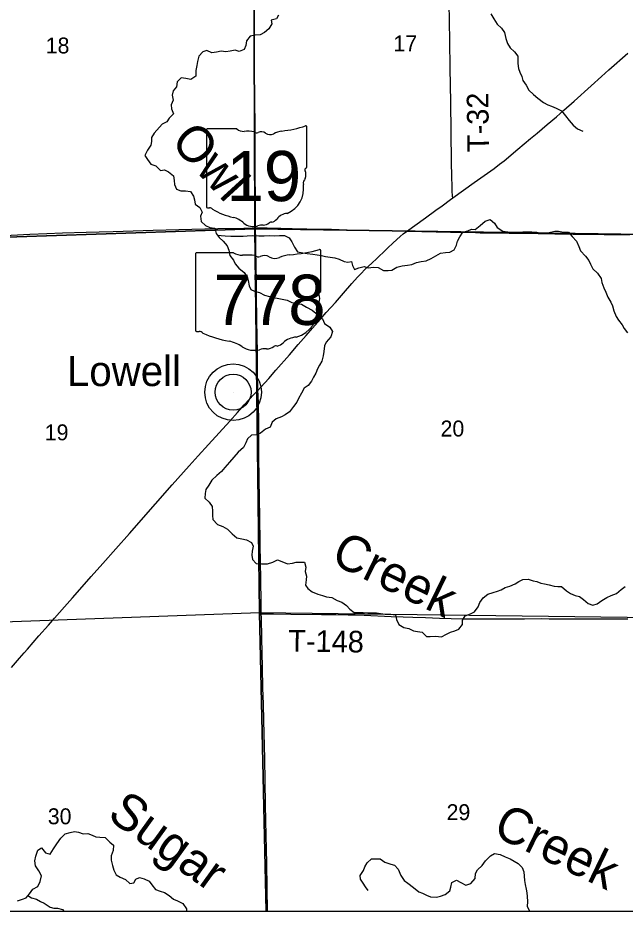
# Model space of a CAD drawing. Extents: x -8.5 to 18.7, y -20.3 to 7.
# Drawn here: x -0.081 to 3.109, y -20.262 to -15.571 of the extents above; entities that cross this region are included whole.
import ezdxf

# ---------------------------------------------------------------- set-up
doc = ezdxf.new("R2010")
doc.units = 0
for name, color, linetype in [('GM_X_Corporation', 7, 'Continuous'), ('GM_X_County_Road', 7, 'Continuous'), ('GM_X_Minor_River', 7, 'Continuous'), ('GM_X_Minor_River_Text', 7, 'Continuous'), ('GM_X_Section', 7, 'Continuous'), ('GM_X_Section_Text', 7, 'Continuous'), ('GM_X_State_Location', 7, 'Continuous'), ('GM_X_State_Route', 7, 'Continuous'), ('GM_X_State_Shield', 7, 'Continuous'), ('GM_X_Township_Road', 7, 'Continuous'), ('GM_X_Township_Road_Text', 7, 'Continuous'), ('GM_X_Unincorporated', 7, 'Continuous'), ('GM_X_Unincorporated_Location', 7, 'Continuous'), ('GM_X_Unincorporated_Text', 7, 'Continuous'), ('SH_Cut_Line', 7, 'Continuous')]:
    doc.layers.add(name, color=color, linetype=linetype)

msp = doc.modelspace()

# ---------------------------------------------------------------- linework, layer by layer
at = {"layer": 'GM_X_Corporation'}
msp.add_lwpolyline([(-0.9232, -20.262), (11.2623, -20.262)], dxfattribs=at)
at = {"layer": 'GM_X_County_Road'}
for points in [[(-0.9189, -16.7512), (-0.8687, -16.7484), (-0.7929, -16.7446), (-0.6837, -16.7394), (-0.6166, -16.736), (-0.5359, -16.7323), (-0.4601, -16.7286), (-0.3458, -16.7228), (-0.287, -16.7201), (-0.2055, -16.7163), (-0.116, -16.7121), (-0.0179, -16.7075), (0.0715, -16.7031), (0.1534, -16.6994), (0.2785, -16.696), (0.3466, -16.6941), (0.4206, -16.6919), (0.6304, -16.6865), (0.7656, -16.6828), (0.9699, -16.6773), (1.1066, -16.6748), (1.1685, -16.6738)], [(1.1981, -18.7004), (1.1972, -18.6597), (1.1957, -18.5019), (1.1947, -18.4473), (1.1926, -18.3219), (1.1904, -18.1964), (1.1886, -18.0939), (1.1869, -17.9965), (1.1854, -17.8676), (1.1849, -17.7758), (1.1845, -17.6854), (1.1832, -17.6048), (1.1826, -17.5813), (1.1822, -17.5672), (1.1812, -17.5528), (1.1797, -17.527)], [(1.231, -20.262), (1.231, -20.2608), (1.2288, -20.1418), (1.2264, -20.0098), (1.2235, -19.8645), (1.2204, -19.7054), (1.2189, -19.5776), (1.216, -19.4624), (1.2113, -19.2613), (1.2092, -19.1755), (1.207, -19.0885), (1.2045, -18.9816), (1.2011, -18.8275), (1.1986, -18.7219), (1.1981, -18.7004)]]:
    msp.add_lwpolyline(points, dxfattribs=at)
at = {"layer": 'GM_X_Minor_River'}
for points in [[(1.2878, -15.5558), (1.2779, -15.5754), (1.2506, -15.5821), (1.2528, -15.6019), (1.2375, -15.6276), (1.2154, -15.6472), (1.1919, -15.6599), (1.1654, -15.662), (1.1396, -15.6672), (1.1198, -15.6921), (1.1174, -15.7164), (1.109, -15.7368), (1.0824, -15.7473), (1.0605, -15.7396), (1.034, -15.7462), (1.012, -15.7484), (0.9871, -15.746), (0.9636, -15.7511), (0.9378, -15.7548), (0.9114, -15.7425), (0.8902, -15.7484), (0.8697, -15.7718), (0.8627, -15.7999), (0.8595, -15.8211), (0.8548, -15.8476), (0.8539, -15.8772), (0.8273, -15.8952), (0.8024, -15.8883), (0.7767, -15.8858), (0.7561, -15.9062), (0.7529, -15.932), (0.7354, -15.9546), (0.7307, -15.9766), (0.7344, -16.0024), (0.7251, -16.0281), (0.7265, -16.0479), (0.7377, -16.0745), (0.7141, -16.0971), (0.7012, -16.1175), (0.6776, -16.1287), (0.635, -16.1755), (0.6205, -16.1997), (0.6211, -16.2194), (0.6187, -16.2391), (0.5997, -16.2663), (0.5866, -16.2936), (0.6001, -16.3149), (0.6182, -16.3385)], [(2.4032, -15.5492), (2.419, -15.5766), (2.437, -15.6041), (2.4595, -15.6239), (2.4753, -15.6483), (2.4827, -15.6786), (2.4909, -15.7045), (2.5051, -15.7288), (2.5284, -15.7494), (2.5457, -15.7715), (2.5463, -15.7905), (2.5462, -15.8095), (2.5491, -15.836), (2.5566, -15.855), (2.5663, -15.8794), (2.5714, -15.8991), (2.5887, -15.9242), (2.6044, -15.9501), (2.6278, -15.9738), (2.6503, -15.9929), (2.6812, -16.0143), (2.7031, -16.0273), (2.7227, -16.0342), (2.7476, -16.0457), (2.7748, -16.0588), (2.7966, -16.0855), (2.8161, -16.1091), (2.8372, -16.1335), (2.8598, -16.1541), (2.8869, -16.1664)], [(0.6182, -16.3385), (0.6446, -16.3478), (0.6687, -16.3714), (0.6891, -16.3685), (0.711, -16.38), (0.7366, -16.3999), (0.741, -16.4242), (0.7416, -16.4454), (0.7528, -16.4705), (0.7747, -16.4797), (0.8005, -16.4783), (0.8254, -16.4823), (0.8427, -16.5066), (0.8478, -16.5256), (0.8515, -16.5499), (0.8748, -16.566), (0.8868, -16.5911), (0.8791, -16.6123), (0.882, -16.6404), (0.9053, -16.661), (0.9279, -16.6725), (0.9537, -16.6749), (0.9611, -16.703), (0.9761, -16.7243), (0.9979, -16.7442), (1.0189, -16.7686), (1.0271, -16.7906), (1.0323, -16.8179), (1.0518, -16.8431), (1.0615, -16.8629), (1.0803, -16.8857), (1.1074, -16.9086), (1.1232, -16.9315), (1.1291, -16.9505), (1.1343, -16.9778), (1.1425, -16.9976), (1.1621, -17.0068), (1.1893, -17.013), (1.2149, -17.0276), (1.2406, -17.0345), (1.2603, -17.04), (1.2807, -17.0431), (1.3079, -17.0486), (1.3336, -17.0533), (1.3585, -17.0663), (1.3834, -17.0702), (1.4099, -17.0749), (1.4363, -17.0895), (1.4649, -17.1056), (1.4935, -17.1285), (1.5191, -17.1507), (1.5296, -17.175), (1.5575, -17.1956), (1.5717, -17.2177), (1.5632, -17.2465), (1.5396, -17.2736), (1.5297, -17.2933), (1.5265, -17.3221), (1.5233, -17.3456), (1.5156, -17.3736), (1.5033, -17.394), (1.4941, -17.4144), (1.4842, -17.4364), (1.4727, -17.4575), (1.4612, -17.4795), (1.4452, -17.5021), (1.4239, -17.5149), (1.4094, -17.5414), (1.3941, -17.5693), (1.3841, -17.5898), (1.3666, -17.6109), (1.3468, -17.6396), (1.324, -17.6554), (1.3042, -17.6659), (1.2769, -17.6764), (1.2556, -17.6944), (1.2441, -17.7209), (1.2206, -17.7314), (1.1933, -17.7525), (1.1728, -17.76), (1.1463, -17.7628), (1.1265, -17.7817), (1.1173, -17.8029), (1.1043, -17.8263), (1.0769, -17.8512), (1.0541, -17.8776), (1.0304, -17.9048), (1.0061, -17.9319), (0.9893, -17.9523), (0.9642, -17.9734), (0.9391, -17.9983), (0.9223, -18.0247), (0.9063, -18.0482), (0.9039, -18.0694), (0.9022, -18.0929), (0.924, -18.115), (0.9398, -18.1363), (0.9419, -18.1606), (0.941, -18.1841), (0.9432, -18.2046), (0.9687, -18.232)], [(0.9673, -16.7118), (0.9875, -16.7138), (1.0079, -16.7147), (1.0382, -16.7163), (1.0624, -16.7172), (1.1032, -16.7175), (1.1244, -16.7161), (1.154, -16.7132), (1.185, -16.7149), (1.213, -16.7151), (1.2417, -16.7137), (1.2675, -16.7146), (1.2932, -16.7133), (1.3197, -16.7142), (1.3438, -16.7264), (1.3581, -16.7477), (1.3723, -16.7744), (1.3888, -16.7995), (1.416, -16.805), (1.4387, -16.8089), (1.4682, -16.8113), (1.4916, -16.8145), (1.5143, -16.8192), (1.5347, -16.8246), (1.5596, -16.8278), (1.5853, -16.8302), (1.608, -16.8387), (1.6329, -16.851), (1.6525, -16.8541), (1.6722, -16.8504), (1.6767, -16.8709), (1.6886, -16.8915), (1.7106, -16.8833), (1.7387, -16.8773), (1.7598, -16.8835), (1.7871, -16.8799), (1.812, -16.8816), (1.8399, -16.8976), (1.8642, -16.8978), (1.8838, -16.8964), (1.9104, -16.8798), (1.9377, -16.8732), (1.9665, -16.8703), (1.9884, -16.8651), (2.0127, -16.8562), (2.0377, -16.851), (2.065, -16.8474), (2.0908, -16.8338), (2.1143, -16.8211), (2.1401, -16.8068), (2.1651, -16.8032), (2.1886, -16.801), (2.2106, -16.7883), (2.2228, -16.7648), (2.2283, -16.7436), (2.2413, -16.7209), (2.2573, -16.696), (2.2831, -16.6886), (2.302, -16.6803), (2.3225, -16.682), (2.3475, -16.6616), (2.3742, -16.6375), (2.3999, -16.6293), (2.4225, -16.6484), (2.4368, -16.6712), (2.4669, -16.6904), (2.4941, -16.6951), (2.5237, -16.696), (2.5448, -16.6961), (2.5721, -16.694), (2.5925, -16.6941), (2.619, -16.695), (2.6432, -16.6967), (2.6629, -16.7006), (2.6848, -16.7037), (2.7098, -16.6971), (2.7393, -16.6904), (2.759, -16.6905), (2.7862, -16.696), (2.8127, -16.6969), (2.8315, -16.719), (2.8548, -16.7426), (2.866, -16.7715), (2.8749, -16.7943), (2.902, -16.8218), (2.9193, -16.8454), (2.9283, -16.8644), (2.9395, -16.8895), (2.9651, -16.9116), (2.983, -16.9398), (2.9875, -16.9611), (2.9971, -16.9877), (3.0076, -17.0105), (3.018, -17.0378), (3.0338, -17.0637), (3.0435, -17.0835), (3.0509, -17.1101), (3.0628, -17.1397), (3.0748, -17.1588), (3.0936, -17.1824), (3.1041, -17.2014)], [(3.1041, -17.2014), (3.1221, -17.2242)], [(0.9687, -18.232), (0.9952, -18.2428), (1.0208, -18.2558), (1.0456, -18.2803), (1.0697, -18.3009), (1.0962, -18.3071), (1.1196, -18.3118), (1.1468, -18.3256), (1.1557, -18.3446), (1.151, -18.3711), (1.1486, -18.3923), (1.1515, -18.4158), (1.1718, -18.4364), (1.1998, -18.4374), (1.2301, -18.4383), (1.2581, -18.4286), (1.2832, -18.4174), (1.3058, -18.4258), (1.336, -18.4381), (1.3618, -18.4352), (1.3815, -18.4293), (1.4011, -18.4286), (1.4254, -18.4288), (1.4328, -18.4554), (1.4288, -18.4789), (1.4355, -18.5032), (1.4331, -18.5229), (1.4307, -18.5494), (1.4434, -18.5684), (1.4653, -18.5845), (1.4955, -18.5968), (1.5204, -18.6045), (1.5408, -18.6114), (1.5695, -18.6146), (1.5967, -18.6307), (1.6208, -18.6392), (1.645, -18.656), (1.663, -18.6766), (1.6864, -18.6934), (1.706, -18.6935), (1.734, -18.6944), (1.7575, -18.6953), (1.7771, -18.6962), (1.8029, -18.6956), (1.8248, -18.6988), (1.849, -18.7019), (1.877, -18.7028), (1.9027, -18.706), (1.9086, -18.7311), (1.9206, -18.7562), (1.9469, -18.773), (1.9726, -18.7785), (1.9975, -18.7892), (2.0187, -18.7931), (2.0437, -18.7963), (2.0655, -18.8199), (2.0851, -18.8201), (2.1124, -18.8172), (2.1442, -18.8211), (2.1715, -18.8069), (2.1927, -18.7972), (2.2147, -18.7897), (2.2352, -18.7815), (2.2543, -18.7573), (2.2559, -18.7338), (2.2697, -18.7111), (2.2977, -18.7014), (2.3175, -18.6902), (2.3373, -18.663), (2.3457, -18.641), (2.3633, -18.6169), (2.3876, -18.5965), (2.4164, -18.5884), (2.4384, -18.5824), (2.4581, -18.5742), (2.4801, -18.5629), (2.5029, -18.5547), (2.531, -18.5428), (2.5515, -18.53), (2.5727, -18.5202), (2.6007, -18.5189), (2.6264, -18.5266), (2.646, -18.5313), (2.6664, -18.539), (2.6861, -18.5429), (2.711, -18.5491), (2.7367, -18.5553), (2.7564, -18.5562), (2.776, -18.5563), (2.8016, -18.5792), (2.822, -18.5945), (2.8476, -18.6052), (2.8703, -18.6092), (2.8914, -18.6252), (2.9155, -18.6466), (2.9404, -18.6543), (2.9632, -18.6476), (2.9875, -18.631), (3.0133, -18.6153), (3.0361, -18.6048), (3.0641, -18.5936)], [(3.0641, -18.5936), (3.0885, -18.5732), (3.1097, -18.5567)], [(0.1066, -19.9349), (0.1234, -19.9085), (0.1448, -19.8791), (0.1676, -19.8564), (0.1934, -19.8482), (0.2161, -19.8431), (0.2373, -19.8477), (0.2622, -19.8554), (0.2864, -19.8541), (0.3098, -19.8625), (0.3295, -19.871), (0.3506, -19.8734), (0.3771, -19.8751), (0.4027, -19.9002), (0.4223, -19.9155), (0.4206, -19.9435), (0.4098, -19.9723), (0.4097, -19.9951), (0.4171, -20.0216), (0.4238, -20.0474), (0.4357, -20.0718), (0.4561, -20.084), (0.4855, -20.0963), (0.5073, -20.1162), (0.5293, -20.1133), (0.5385, -20.0936), (0.5582, -20.0846), (0.5831, -20.0931), (0.6088, -20.1054), (0.6223, -20.1244), (0.6418, -20.148), (0.6675, -20.158), (0.6902, -20.1635), (0.7135, -20.1795), (0.7361, -20.1986), (0.758, -20.2071), (0.7867, -20.2224), (0.8047, -20.2505), (0.8053, -20.262)], [(-0.0834, -20.2084), (-0.0569, -20.1987), (-0.0372, -20.192), (-0.0204, -20.1708), (-0.0013, -20.1467), (0.0245, -20.1324), (0.036, -20.1059), (0.043, -20.0764), (0.0288, -20.0505), (0.0123, -20.0247), (0.0086, -19.9981), (0.0133, -19.9739), (0.0241, -19.9413), (0.0438, -19.93), (0.0641, -19.9552), (0.0898, -19.9622), (0.1066, -19.9349)], [(1.7594, -20.1536), (1.7451, -20.1345), (1.7331, -20.1155), (1.7197, -20.0942), (1.7175, -20.0745), (1.7351, -20.0488), (1.7427, -20.0291), (1.7542, -20.0087), (1.7763, -19.9876), (1.8232, -19.9879), (1.8466, -20.0047), (1.8783, -20.0162), (1.8979, -20.0201), (1.9175, -20.0422), (1.9316, -20.0749), (1.9481, -20.1008), (1.9685, -20.1146), (1.9971, -20.1382), (2.025, -20.1604), (2.0446, -20.1681), (2.0657, -20.178), (2.0876, -20.1873), (2.1186, -20.1882), (2.1398, -20.1838), (2.1641, -20.174), (2.1884, -20.1552), (2.1946, -20.1355), (2.1985, -20.1113), (2.2243, -20.0986), (2.2469, -20.1123), (2.2718, -20.1254), (2.2984, -20.1172), (2.3212, -20.0908), (2.3229, -20.065), (2.3344, -20.0453), (2.3587, -20.022), (2.3763, -19.997), (2.4029, -19.9722), (2.4234, -19.9594), (2.4536, -19.9641), (2.4801, -19.9772), (2.505, -19.9879), (2.5261, -19.9994), (2.5479, -20.0117), (2.569, -20.033), (2.5772, -20.055), (2.5786, -20.0778), (2.5807, -20.1013), (2.5844, -20.1218), (2.5895, -20.1469), (2.5924, -20.1666), (2.5946, -20.1856), (2.5959, -20.2106), (2.595, -20.2371), (2.6078, -20.2599), (2.608, -20.262)], [(-0.028, -20.1804), (-0.0099, -20.1914), (0.0165, -20.1991), (0.0376, -20.2106), (0.058, -20.2206), (0.0882, -20.2404), (0.1078, -20.2459), (0.1275, -20.246), (0.1532, -20.2529), (0.1602, -20.262)]]:
    msp.add_lwpolyline(points, dxfattribs=at)
at = {"layer": 'GM_X_Section'}
for points in [[(-0.8797, -14.6721), (1.1578, -14.6567), (1.1642, -16.6782), (-0.9213, -16.7479), (-0.9212, -16.7237), (-0.8807, -14.7032)], [(1.1578, -14.6567), (3.1911, -14.698), (3.2075, -16.709), (1.1642, -16.6782)], [(-0.9213, -16.7479), (1.1642, -16.6782), (1.1889, -18.696), (-0.9278, -18.7724), (-0.9282, -18.7246)], [(1.1642, -16.6782), (3.2075, -16.709), (3.2579, -18.7225), (1.1889, -18.696)]]:
    msp.add_lwpolyline(points, close=True, dxfattribs=at)
at = {"layer": 'GM_X_State_Route'}
for points in [[(1.1685, -16.6738), (1.1685, -16.6459), (1.1675, -16.5191), (1.1668, -16.3935), (1.1656, -16.2705), (1.1655, -16.1909), (1.1636, -15.9534), (1.1632, -15.8868), (1.1625, -15.7608), (1.1618, -15.6286), (1.1612, -15.5023), (1.1612, -15.3717), (1.1607, -15.2871), (1.1598, -15.1492), (1.1596, -15.0771), (1.1597, -14.9192), (1.159, -14.7477), (1.1594, -14.6622)], [(-0.1139, -18.9818), (-0.0714, -18.9331), (-0.0469, -18.905), (-0.0306, -18.8863), (-0.0003, -18.8516), (0.03, -18.817), (0.0798, -18.7599), (0.1117, -18.7233), (0.1644, -18.6637), (0.2064, -18.6162), (0.2686, -18.5452), (0.3048, -18.5042), (0.3653, -18.4365), (0.4334, -18.359), (0.505, -18.2779), (0.6419, -18.1234), (0.7305, -18.0226), (0.8193, -17.9236), (0.8671, -17.8712), (0.921, -17.811), (1.0334, -17.6881), (1.073, -17.6434), (1.1087, -17.6037), (1.1599, -17.5477), (1.1797, -17.527), (1.1951, -17.511), (1.2172, -17.4873), (1.2371, -17.4651), (1.2743, -17.4217), (1.3456, -17.3404), (1.3921, -17.2869), (1.4343, -17.238), (1.4678, -17.1996), (1.509, -17.1532), (1.5395, -17.1187), (1.5872, -17.0648), (1.6298, -17.0161), (1.6738, -16.9655), (1.7037, -16.9323), (1.7242, -16.9107), (1.741, -16.8941), (1.78, -16.8574), (1.8034, -16.8354), (1.8135, -16.8259), (1.8441, -16.7971), (1.8629, -16.7791), (1.8891, -16.7543), (1.9105, -16.7338), (1.9274, -16.719), (1.9429, -16.7054), (1.9608, -16.692), (2.0607, -16.6202), (2.1153, -16.5812), (2.1476, -16.5579), (2.1929, -16.525), (2.2048, -16.5165), (2.3172, -16.4361), (2.4212, -16.3613), (2.45, -16.3394), (2.4733, -16.3208), (2.546, -16.2604), (2.6115, -16.205), (2.6469, -16.1756), (2.7005, -16.1312), (2.7486, -16.0898), (2.7869, -16.0562), (2.841, -16.0085), (2.9309, -15.9281), (2.9854, -15.879), (3.0243, -15.8442), (3.1234, -15.7555)], [(3.1349, -16.7108), (2.9993, -16.71), (2.9186, -16.7091), (2.8365, -16.7076), (2.7408, -16.7062), (2.6525, -16.7051), (2.5742, -16.7039), (2.4997, -16.7028), (2.4387, -16.7022), (2.3815, -16.7014), (2.348, -16.7008), (2.3231, -16.7004), (2.1927, -16.6982), (2.0411, -16.6941), (1.9608, -16.692), (1.9194, -16.6909), (1.8311, -16.6893), (1.7441, -16.6866), (1.6497, -16.6849), (1.5676, -16.6829), (1.4371, -16.6804), (1.3601, -16.6786), (1.3004, -16.6771), (1.2283, -16.6748), (1.1685, -16.6738)], [(1.1797, -17.527), (1.1796, -17.5159), (1.1789, -17.4487), (1.1774, -17.3331), (1.1764, -17.2412), (1.1749, -17.1629), (1.1734, -17.0226), (1.1723, -16.9506), (1.1711, -16.881), (1.1692, -16.7804), (1.1686, -16.7394), (1.1685, -16.6738)]]:
    msp.add_lwpolyline(points, dxfattribs=at)
at = {"layer": 'GM_X_State_Shield'}
for p, q in [((0.91, -16.1612), (0.91, -16.5614)), ((1.0696, -16.1543), (0.9152, -16.1543)), ((1.4373, -16.3538), (1.4373, -16.1444)), ((1.4373, -16.3537), (1.4373, -16.3538)), ((1.5114, -17.0038), (1.5114, -16.7944)), ((0.8522, -16.8112), (0.8522, -17.2114)), ((1.0517, -16.8043), (0.8587, -16.8043)), ((1.5113, -17.0037), (1.5114, -17.0038))]:
    msp.add_line(p, q, dxfattribs=at)
for centre, radius, start, end in [((1.2495, -15.6086), 0.5592, 275.8445, 288.9065), ((1.4315, -16.1435), 0.00587, 351.8621, 97.738), ((0.916, -16.1603), 0.00611, 98.1301, 188.1301), ((1.1064, -16.1078), 0.0593, 231.6195, 271.1119), ((1.126, -16.379), 0.2127, 80.4867, 94.9883), ((1.1743, -16.1583), 0.0171, 219.7921, 297.1024), ((1.1994, -16.2045), 0.0355, 54.4667, 119.1411), ((1.2453, -16.1411), 0.0428, 233.8562, 294.8282), ((1.3208, -16.2765), 0.1125, 97.3462, 120.7689), ((1.436, -16.3691), 0.00909, 107.944, 210.337), ((1.4311, -16.3546), 0.00628, 289.6038, 7.7341), ((1.4584, -16.4414), 0.0397, 136.8065, 186.9296), ((1.3782, -16.3956), 0.0545, 340.033, 23.6496), ((1.2808, -16.468), 0.1399, 292.3089, 8.9858), ((0.9161, -16.5623), 0.00616, 171.9584, 258.3066), ((0.917, -16.5214), 0.047, 267.339, 280.6039), ((0.9267, -16.5845), 0.017, 29.7484, 93.2717), ((1.1408, -16.2249), 0.4038, 240.4129, 257.1985), ((1.3398, -16.6738), 0.0766, 94.4031, 142.5768), ((1.0204, -16.7412), 0.1264, 47.1842, 75.836), ((1.157, -16.5865), 0.0802, 230.7004, 286.2918), ((1.2092, -16.6165), 0.0427, 268.777, 315.5493), ((1.2479, -16.6552), 0.012, 65.7517, 132.6484), ((1.2427, -16.6002), 0.0452, 282.8732, 323.2771), ((1.2034, -16.7249), 0.0659, 85.6951, 111.2099)]:
    msp.add_arc(centre, radius, start, end, dxfattribs=at)
for centre, major_axis, start_param, end_param in [((1.2766, -16.2586), (0.699, 0), 4.814394, 5.042369), ((1.5041, -16.7935), (0.00734, 0), 6.141152, 7.989035), ((0.8598, -16.8103), (0.00764, 0), 1.712693, 3.28349), ((1.0977, -16.7578), (0.0741, 0), 4.042523, 4.731795), ((1.1223, -17.029), (0.2659, 0), 1.404758, 1.657858), ((1.1826, -16.8083), (0.0214, 0), 3.836095, 5.185415), ((1.214, -16.8545), (0.0444, 0), 0.950623, 2.079405), ((1.2714, -16.7911), (0.0534, 0), 4.081561, 5.145723), ((1.3657, -16.9265), (0.1406, 0), 1.699011, 2.107814), ((1.5097, -17.0191), (0.0114, 0), 1.883978, 3.671073), ((1.4374, -17.0456), (0.0682, 0), 5.934695, 6.695948), ((1.5036, -17.0046), (0.00785, 0), 5.05454, 6.418171), ((1.5377, -17.0914), (0.0496, 0), 2.387724, 3.262537), ((1.3157, -17.118), (0.1748, 0), 5.101752, 6.440018), ((0.8598, -17.2123), (0.0077, 0), 3.00124, 4.508301), ((0.873, -17.2345), (0.0212, 0), 0.519207, 1.627899), ((0.861, -17.1714), (0.0588, 0), 4.665946, 4.897461), ((1.1407, -16.8749), (0.5048, 0), 4.195997, 4.488961), ((1.3895, -17.3238), (0.0958, 0), 1.647645, 2.488434), ((0.9902, -17.3912), (0.1579, 0), 0.823519, 1.323587), ((1.161, -17.2365), (0.1002, 0), 4.026481, 4.996735), ((1.2189, -17.3749), (0.0824, 0), 1.495662, 1.94098), ((1.2262, -17.2665), (0.0534, 0), 4.691044, 5.507374), ((1.2745, -17.3052), (0.015, 0), 1.147584, 2.315152), ((1.2681, -17.2502), (0.0565, 0), 4.937069, 5.64225)]:
    msp.add_ellipse(centre, major_axis=major_axis, ratio=0.8, start_param=start_param, end_param=end_param, dxfattribs=at)
at = {"layer": 'GM_X_Township_Road'}
for points in [[(2.2048, -16.5165), (2.203, -16.5075), (2.2017, -16.497), (2.2008, -16.4887), (2.2001, -16.4559), (2.1992, -16.4037), (2.1979, -16.3291), (2.1953, -16.1687), (2.1931, -16.0134), (2.1906, -15.8356), (2.1886, -15.6914), (2.1872, -15.5894), (2.1857, -15.4912)], [(1.1981, -18.7004), (1.2094, -18.7004), (1.2629, -18.7006), (1.3536, -18.7015), (1.514, -18.7036), (1.5898, -18.7049), (1.6544, -18.7054), (1.6905, -18.7062), (1.7377, -18.7078), (1.8805, -18.7144), (1.9439, -18.7162), (1.9936, -18.7183), (2.0607, -18.7205), (2.134, -18.7229), (2.1949, -18.7248), (2.2533, -18.7263), (2.3155, -18.7268), (2.3863, -18.7266), (2.5069, -18.7268), (2.5815, -18.7264), (2.6686, -18.7258), (2.7096, -18.7262), (2.7879, -18.7264), (2.9719, -18.7265), (3.0353, -18.7262), (3.1236, -18.7262)]]:
    msp.add_lwpolyline(points, dxfattribs=at)
at = {"layer": 'GM_X_Unincorporated'}
for radius in [0.1488, 0.0943]:
    msp.add_circle((1.05, -17.5366), radius, dxfattribs=at)
at = {"layer": 'GM_X_Unincorporated_Location'}
msp.add_line((1.05, -17.5366), (1.05, -17.5366), dxfattribs=at)
at = {"layer": 'GM_X_Unincorporated_Text'}
for points in [[(-0.9268, -20.262), (1.2233, -20.262), (1.1889, -18.696), (-0.9278, -18.7724)], [(1.2233, -20.262), (3.2635, -20.262), (3.2579, -18.7225), (1.1889, -18.696)]]:
    msp.add_lwpolyline(points, close=True, dxfattribs=at)
at = {"layer": 'SH_Cut_Line'}
msp.add_lwpolyline([(-8.4587, -10.6981), (-8.4587, -20.262), (18.7413, -20.262), (18.7413, -10.9039)], dxfattribs=at)

# ---------------------------------------------------------------- texts
at = {"layer": 'GM_X_Minor_River_Text'}
for s, height, rotation, p in [('Owl', 0.1895, 312.4193, (0.7158, -16.2258)), ('Creek', 0.18948, 334.1943, (1.5557, -18.4304)), ('Sugar', 0.18947, 324.1972, (0.382, -19.7713)), ('Creek', 0.18947, 334.1986, (2.4067, -19.8601))]:
    msp.add_text(s, height=height, rotation=rotation, dxfattribs=at).set_placement(p)
at = {"layer": 'GM_X_Section_Text'}
for s, p in [('17', (1.8923, -15.7465)), ('18', (0.0657, -15.7576)), ('20', (2.1398, -17.7693)), ('19', (0.0607, -17.7893)), ('29', (2.1715, -19.7842)), ('30', (0.0765, -19.8059))]:
    msp.add_text(s, height=0.08371, rotation=0, dxfattribs=at).set_placement(p)
at = {"layer": 'GM_X_State_Location'}
for s, p in [('19', (1.0723, -16.4155)), ('778', (1.0407, -17.0655))]:
    msp.add_text(s, height=0.000379, rotation=0, dxfattribs=at).set_placement(p)
for s, p in [('s', (1.1677, -16.3879)), ('r', (1.1677, -16.3879)), ('s', (1.1744, -17.0379)), ('r', (1.1744, -17.0379))]:
    msp.add_text(s, height=0.000379, dxfattribs=at).set_placement(p)
at = {"layer": 'GM_X_State_Shield'}
for s, p in [('19', (1.0152, -16.5332)), ('778', (0.9474, -17.1832))]:
    msp.add_text(s, height=0.26367, dxfattribs=at).set_placement(p)
at = {"layer": 'GM_X_Township_Road_Text'}
for s, rotation, p in [('T-32', 90.7065, (2.3945, -16.2748)), ('T-148', 359.1773, (1.3392, -18.8983))]:
    msp.add_text(s, height=0.11364, rotation=rotation, dxfattribs=at).set_placement(p)
at = {"layer": 'GM_X_Unincorporated_Text'}
msp.add_text('Lowell', height=0.15795, rotation=0, dxfattribs=at).set_placement((0.1773, -17.5045))

doc.saveas('drawing.dxf')
